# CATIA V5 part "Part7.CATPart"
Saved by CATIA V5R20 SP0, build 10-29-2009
Part number: Part7
Bounding box of the stored display mesh (mm): x 0 to 3, y -7.5 to 7.5, z -7.312 to 7.312
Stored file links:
  C:\Users\YS\Desktop\독수리\Part7.CATPart
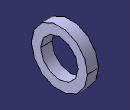
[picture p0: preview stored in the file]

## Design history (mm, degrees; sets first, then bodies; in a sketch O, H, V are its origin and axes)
Body1 (main body)
  Sketch1 on yz-plane, origin (0, 0, 0), H (0, 1, 0), V (0, 0, 1)
    circle A1 centre (0, 0) radius 5
    circle A2 centre (0, 0) radius 7.5
    radius A1 = 5
    radius A2 = 7.5
  Pad1: profile Sketch1, direction (1, 0, 0), length 3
